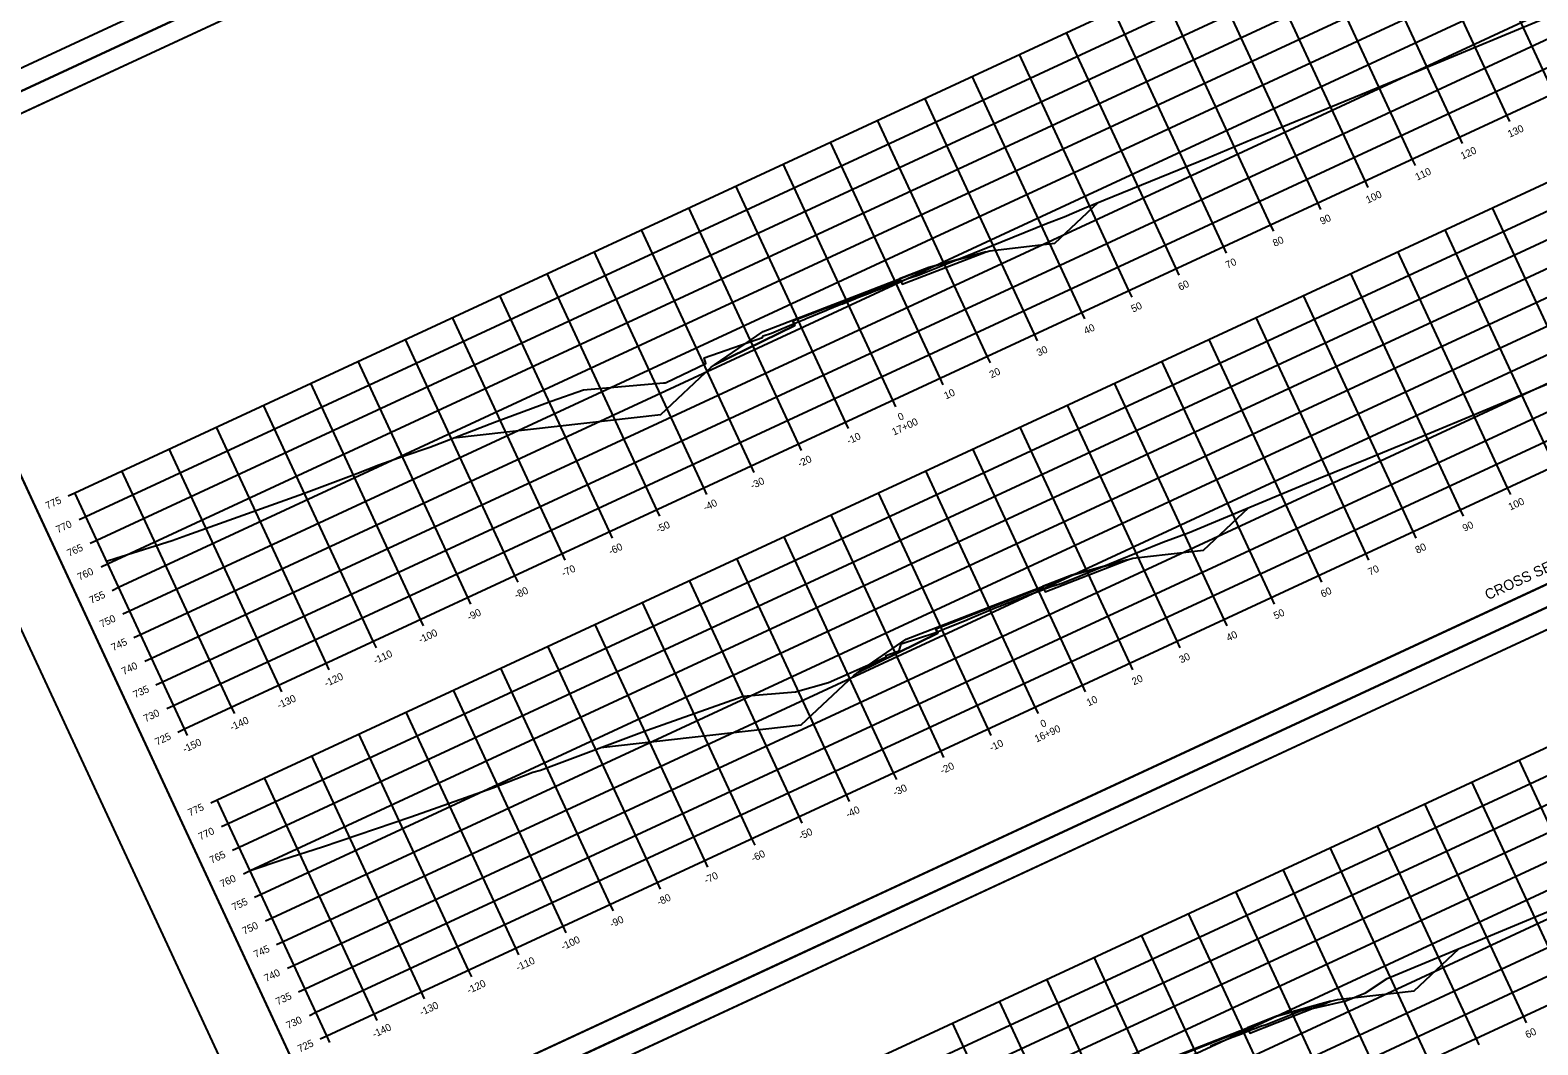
# Model space of a CAD drawing. Extents: x 1354696 to 1366163, y 660729 to 670380.
# Drawn here: x 1358133.8 to 1358423.4, y 665571.2 to 665766.1 of the extents above; entities that cross this region are included whole.
import ezdxf

# ---------------------------------------------------------------- set-up
doc = ezdxf.new("R2010")
doc.units = 0
for name, color, linetype in [('Default', 7, 'Continuous'), ('R_Alt Surface', 7, 'Continuous'), ('R_Axis', 7, 'Continuous'), ('R_Axis Annot', 7, 'Continuous'), ('R_Border', 7, 'Continuous'), ('R_Draft', 7, 'Continuous'), ('R_Exist Surface', 7, 'Continuous'), ('R_Fin Surface', 7, 'Continuous'), ('R_Grid', 7, 'Continuous'), ('R_No Plot', 7, 'Continuous')]:
    doc.layers.add(name, color=color, linetype=linetype)

msp = doc.modelspace()

# ---------------------------------------------------------------- linework, layer by layer
at = {"layer": 'Default'}
for points in [[(1358301.32, 665717.32), (1358317.44, 665723.54), (1358306.44, 665720.5), (1358300.83, 665718.34), (1358300.91, 665718.18)], [(1358280.33, 665710.25), (1358280.72, 665709.38), (1358265.28, 665701.83), (1358274.65, 665708.24), (1358280.26, 665710.4)], [(1358328.75, 665658.24), (1358344.58, 665664.39), (1358333.87, 665661.43), (1358328.26, 665659.26), (1358328.34, 665659.1)], [(1358307.79, 665651.12), (1358308.18, 665650.25), (1358292.83, 665642.75), (1358302.11, 665649.09), (1358307.72, 665651.27)], [(1358368.1, 665573.47), (1358383.66, 665579.56), (1358373.22, 665576.68), (1358367.62, 665574.48), (1358367.69, 665574.33)]]:
    msp.add_lwpolyline(points, close=True, dxfattribs=at)
at = {"layer": 'R_Alt Surface'}
for points in [[(1358265.28, 665701.83), (1358280.72, 665709.38), (1358280.33, 665710.25), (1358290.62, 665714.22), (1358300.91, 665718.18), (1358301.32, 665717.32), (1358317.44, 665723.54)], [(1358292.83, 665642.75), (1358308.18, 665650.25), (1358307.79, 665651.12), (1358318.06, 665655.11), (1358328.34, 665659.1), (1358328.75, 665658.24), (1358344.58, 665664.39)], [(1358332.31, 665557.97), (1358347.56, 665565.42), (1358347.17, 665566.29), (1358357.43, 665570.31), (1358367.69, 665574.33), (1358368.1, 665573.47), (1358383.66, 665579.56)]]:
    msp.add_lwpolyline(points, dxfattribs=at)
at = {"layer": 'R_Axis'}
for p, q in [((1358163.47, 665631.88), (1358435.57, 665758.21)), ((1358418.02, 665748.52), (1358417.43, 665749.79)), ((1358408.95, 665744.31), (1358408.36, 665745.58)), ((1358399.88, 665740.09), (1358399.29, 665741.36)), ((1358390.81, 665735.88), (1358390.22, 665737.15)), ((1358381.74, 665731.67), (1358381.15, 665732.94)), ((1358372.67, 665727.46), (1358372.08, 665728.73)), ((1358363.6, 665723.25), (1358363.01, 665724.52)), ((1358354.53, 665719.04), (1358353.94, 665720.31)), ((1358345.46, 665714.83), (1358344.87, 665716.1)), ((1358336.39, 665710.62), (1358335.8, 665711.89)), ((1358327.32, 665706.41), (1358326.73, 665707.68)), ((1358318.25, 665702.2), (1358317.66, 665703.47)), ((1358190.84, 665572.92), (1358462.94, 665699.25)), ((1358309.18, 665697.98), (1358308.59, 665699.25)), ((1358300.11, 665693.77), (1358299.52, 665695.04)), ((1358291.04, 665689.56), (1358290.45, 665690.83)), ((1358281.97, 665685.35), (1358281.38, 665686.62)), ((1358272.9, 665681.14), (1358272.31, 665682.41)), ((1358141.14, 665676.64), (1358142.41, 665677.23)), ((1358163.47, 665631.88), (1358142.41, 665677.23)), ((1358263.83, 665676.93), (1358263.24, 665678.2)), ((1358418.18, 665676.93), (1358417.59, 665678.2)), ((1358254.76, 665672.72), (1358254.17, 665673.99)), ((1358409.11, 665672.72), (1358408.52, 665673.99)), ((1358143.25, 665672.1), (1358144.52, 665672.69)), ((1358145.36, 665667.57), (1358146.63, 665668.16)), ((1358245.69, 665668.51), (1358245.1, 665669.78)), ((1358400.04, 665668.51), (1358399.45, 665669.78)), ((1358236.62, 665664.3), (1358236.03, 665665.57)), ((1358390.97, 665664.29), (1358390.38, 665665.56)), ((1358147.46, 665663.03), (1358148.73, 665663.62)), ((1358227.55, 665660.09), (1358226.96, 665661.36)), ((1358381.9, 665660.08), (1358381.31, 665661.35)), ((1358149.57, 665658.5), (1358150.84, 665659.09)), ((1358218.48, 665655.87), (1358217.89, 665657.14)), ((1358372.83, 665655.87), (1358372.24, 665657.14)), ((1358151.67, 665653.96), (1358152.94, 665654.55)), ((1358209.41, 665651.66), (1358208.82, 665652.93)), ((1358363.76, 665651.66), (1358363.17, 665652.93)), ((1358153.78, 665649.43), (1358155.05, 665650.02)), ((1358200.34, 665647.45), (1358199.75, 665648.72)), ((1358354.69, 665647.45), (1358354.1, 665648.72)), ((1358155.88, 665644.89), (1358157.15, 665645.48)), ((1358191.27, 665643.24), (1358190.68, 665644.51)), ((1358345.62, 665643.24), (1358345.03, 665644.51)), ((1358157.99, 665640.36), (1358159.26, 665640.95)), ((1358182.2, 665639.03), (1358181.61, 665640.3)), ((1358336.55, 665639.03), (1358335.96, 665640.3)), ((1358160.09, 665635.82), (1358161.36, 665636.41)), ((1358173.13, 665634.82), (1358172.54, 665636.09)), ((1358327.48, 665634.82), (1358326.89, 665636.09)), ((1358162.2, 665631.29), (1358163.47, 665631.88)), ((1358164.06, 665630.61), (1358163.47, 665631.88)), ((1358318.41, 665630.61), (1358317.82, 665631.88)), ((1358309.34, 665626.4), (1358308.75, 665627.67)), ((1358300.27, 665622.18), (1358299.68, 665623.45)), ((1358168.52, 665617.68), (1358169.79, 665618.27)), ((1358190.84, 665572.92), (1358169.79, 665618.27)), ((1358291.2, 665617.97), (1358290.61, 665619.24)), ((1358282.13, 665613.76), (1358281.54, 665615.03)), ((1358170.62, 665613.15), (1358171.89, 665613.74)), ((1358230.15, 665488.26), (1358502.25, 665614.59)), ((1358172.73, 665608.61), (1358174, 665609.2)), ((1358273.06, 665609.55), (1358272.47, 665610.82)), ((1358263.99, 665605.34), (1358263.4, 665606.61)), ((1358174.83, 665604.08), (1358176.1, 665604.67)), ((1358254.92, 665601.13), (1358254.33, 665602.4)), ((1358176.94, 665599.54), (1358178.21, 665600.13)), ((1358245.85, 665596.92), (1358245.26, 665598.19)), ((1358179.04, 665595.01), (1358180.31, 665595.6)), ((1358236.78, 665592.71), (1358236.19, 665593.98)), ((1358181.15, 665590.47), (1358182.42, 665591.06)), ((1358227.71, 665588.5), (1358227.12, 665589.77)), ((1358183.25, 665585.94), (1358184.52, 665586.53)), ((1358218.64, 665584.29), (1358218.05, 665585.56)), ((1358185.36, 665581.4), (1358186.63, 665581.99)), ((1358209.57, 665580.07), (1358208.98, 665581.34)), ((1358187.47, 665576.87), (1358188.74, 665577.46)), ((1358200.5, 665575.86), (1358199.91, 665577.13)), ((1358421.21, 665575.42), (1358420.62, 665576.69)), ((1358189.57, 665572.33), (1358190.84, 665572.92)), ((1358191.43, 665571.65), (1358190.84, 665572.92)), ((1358412.14, 665571.21), (1358411.55, 665572.48))]:
    msp.add_line(p, q, dxfattribs=at)
at = {"layer": 'R_Border'}
for p, q in [((1358388.95, 665878.06), (1358102.17, 665744.91)), ((1358105.49, 665737.77), (1358392.27, 665870.91)), ((1358192.01, 665551.41), (1358105.49, 665737.77)), ((1358478.79, 665684.56), (1358192.01, 665551.41)), ((1358195.32, 665544.27), (1358482.1, 665677.41)), ((1358333.77, 665608.26), (1358333.77, 665608.26)), ((1358333.77, 665608.26), (1358333.77, 665608.26))]:
    msp.add_line(p, q, dxfattribs=at)
at = {"layer": 'R_Exist Surface'}
for points in [[(1358148.5, 665664.11), (1358150.27, 665664.67), (1358161.1, 665668.1), (1358163.96, 665669.09), (1358186.34, 665677.1), (1358196.56, 665680.93), (1358200.84, 665682.61), (1358205.66, 665684.31), (1358210.59, 665686.03), (1358223, 665690.77), (1358233.91, 665694.83), (1358240.09, 665697.02), (1358255.47, 665698.36), (1358255.8, 665698.35), (1358255.99, 665698.44), (1358263.64, 665702.1), (1358263.27, 665703.18), (1358274.5, 665707.04), (1358274.6, 665707.38), (1358276.2, 665707.9), (1358281.01, 665709.95), (1358282.32, 665710.48), (1358282.47, 665710.55), (1358282.89, 665710.71), (1358286.77, 665712.33), (1358287.03, 665712.44), (1358289.56, 665713.44), (1358289.83, 665713.55), (1358292.34, 665714.57), (1358292.62, 665714.68), (1358295.14, 665715.66), (1358295.43, 665715.77), (1358297.97, 665716.71), (1358298.25, 665716.81), (1358302.38, 665718.37), (1358302.55, 665718.44), (1358302.78, 665718.51), (1358304.58, 665719.09), (1358315.14, 665723.3), (1358318.49, 665724.67), (1358329.04, 665728.95), (1358332.43, 665730.25), (1358336.28, 665731.9), (1358360, 665741.59), (1358368.56, 665745.14), (1358382.9, 665751.04), (1358397.76, 665757.21), (1358429.86, 665770.52)], [(1358176.08, 665604.71), (1358182.37, 665606.8), (1358189.99, 665609.21), (1358206.98, 665615), (1358222.73, 665620.59), (1358225.32, 665621.62), (1358230.39, 665623.57), (1358231.86, 665623.96), (1358252.37, 665631.63), (1358270.75, 665638.15), (1358280.82, 665639.03), (1358287.15, 665640.78), (1358296.48, 665644.9), (1358298.26, 665645.75), (1358298.18, 665646), (1358300.76, 665646.89), (1358301.15, 665648.23), (1358307.59, 665650.34), (1358308.36, 665650.67), (1358308.58, 665650.75), (1358309.87, 665651.29), (1358313.3, 665652.66), (1358314.31, 665653.08), (1358316.41, 665654), (1358317.07, 665654.26), (1358319.19, 665655.12), (1358319.85, 665655.39), (1358321.98, 665656.25), (1358322.64, 665656.51), (1358324.79, 665657.33), (1358325.45, 665657.58), (1358327.61, 665658.37), (1358328.69, 665658.78), (1358329.96, 665659.26), (1358331.62, 665659.78), (1358331.98, 665659.89), (1358334.07, 665660.73), (1358342.52, 665664.18), (1358351.39, 665667.77), (1358356.41, 665669.62), (1358381.28, 665679.97), (1358390.65, 665683.77), (1358395.75, 665685.85), (1358396.84, 665686.31), (1358398.74, 665687.09), (1358402.93, 665688.83), (1358410.9, 665692.16), (1358425.9, 665698.43)], [(1358360.5, 665571.03), (1358362.08, 665571.67), (1358363.29, 665572.13), (1358364.89, 665572.74), (1358366.5, 665573.33), (1358368.3, 665574.06), (1358369.23, 665574.41), (1358370.13, 665574.78), (1358371.21, 665575.13), (1358377.6, 665577.65), (1358377.93, 665577.78), (1358378.91, 665578.07), (1358380.36, 665578.22), (1358386.51, 665579.67), (1358390.32, 665581.18), (1358394.46, 665583.93), (1358429.98, 665598.76)]]:
    msp.add_lwpolyline(points, dxfattribs=at)
at = {"layer": 'R_Fin Surface'}
for points in [[(1358215.18, 665687.78), (1358254.99, 665692.3), (1358264.61, 665701.37), (1358265.28, 665701.83), (1358274.65, 665708.24), (1358280.26, 665710.4), (1358290.55, 665714.37), (1358300.83, 665718.34), (1358306.44, 665720.5), (1358317.44, 665723.54), (1358318.17, 665723.74), (1358330.66, 665725.16), (1358338.98, 665733.01)], [(1358243.45, 665628.29), (1358281.93, 665632.66), (1358292.07, 665642.23), (1358292.83, 665642.75), (1358302.11, 665649.09), (1358307.72, 665651.27), (1358317.99, 665655.26), (1358328.26, 665659.26), (1358333.87, 665661.43), (1358344.58, 665664.39), (1358345.59, 665664.67), (1358359.17, 665666.21), (1358367.8, 665674.36)], [(1358284.04, 665543.14), (1358320.77, 665547.3), (1358331.46, 665557.39), (1358332.31, 665557.97), (1358341.5, 665564.25), (1358347.1, 665566.45), (1358357.36, 665570.46), (1358367.62, 665574.48), (1358373.22, 665576.68), (1358383.66, 665579.56), (1358384.94, 665579.92), (1358399.64, 665581.58), (1358408.22, 665589.67)]]:
    msp.add_lwpolyline(points, dxfattribs=at)
at = {"layer": 'R_Grid'}
for p, q in [((1358142.41, 665677.23), (1358414.52, 665803.56)), ((1358144.52, 665672.69), (1358416.62, 665799.02)), ((1358426.5, 665754), (1358405.45, 665799.35)), ((1358146.63, 665668.16), (1358418.73, 665794.49)), ((1358417.43, 665749.79), (1358396.38, 665795.14)), ((1358148.73, 665663.62), (1358420.83, 665789.95)), ((1358408.36, 665745.58), (1358387.31, 665790.93)), ((1358399.29, 665741.36), (1358378.24, 665786.72)), ((1358150.84, 665659.09), (1358422.94, 665785.42)), ((1358152.94, 665654.55), (1358425.05, 665780.88)), ((1358390.22, 665737.15), (1358369.17, 665782.5)), ((1358381.15, 665732.94), (1358360.1, 665778.29)), ((1358155.05, 665650.02), (1358427.15, 665776.35)), ((1358157.15, 665645.48), (1358429.26, 665771.81)), ((1358372.08, 665728.73), (1358351.03, 665774.08)), ((1358363.01, 665724.52), (1358341.96, 665769.87)), ((1358159.26, 665640.95), (1358431.36, 665767.28)), ((1358353.94, 665720.31), (1358332.89, 665765.66)), ((1358161.36, 665636.41), (1358433.47, 665762.74)), ((1358344.87, 665716.1), (1358323.82, 665761.45)), ((1358163.47, 665631.88), (1358435.57, 665758.21)), ((1358335.8, 665711.89), (1358314.75, 665757.24)), ((1358326.73, 665707.68), (1358305.68, 665753.03)), ((1358317.66, 665703.47), (1358296.61, 665748.82)), ((1358169.79, 665618.27), (1358441.89, 665744.6)), ((1358308.59, 665699.25), (1358287.54, 665744.6)), ((1358171.89, 665613.74), (1358444, 665740.07)), ((1358299.52, 665695.04), (1358278.47, 665740.39)), ((1358174, 665609.2), (1358446.1, 665735.53)), ((1358290.45, 665690.83), (1358269.4, 665736.18)), ((1358176.1, 665604.67), (1358448.21, 665731)), ((1358281.38, 665686.62), (1358260.33, 665731.97)), ((1358435.73, 665686.62), (1358414.68, 665731.97)), ((1358178.21, 665600.13), (1358450.31, 665726.46)), ((1358272.31, 665682.41), (1358251.26, 665727.76)), ((1358426.66, 665682.41), (1358405.61, 665727.76)), ((1358263.24, 665678.2), (1358242.19, 665723.55)), ((1358417.59, 665678.2), (1358396.54, 665723.55)), ((1358180.31, 665595.6), (1358452.42, 665721.93)), ((1358254.17, 665673.99), (1358233.12, 665719.34)), ((1358408.52, 665673.99), (1358387.47, 665719.34)), ((1358182.42, 665591.06), (1358454.52, 665717.39)), ((1358245.1, 665669.78), (1358224.05, 665715.13)), ((1358399.45, 665669.78), (1358378.4, 665715.13)), ((1358184.52, 665586.53), (1358456.63, 665712.86)), ((1358236.03, 665665.57), (1358214.98, 665710.92)), ((1358390.38, 665665.56), (1358369.33, 665710.92)), ((1358186.63, 665581.99), (1358458.73, 665708.32)), ((1358226.96, 665661.36), (1358205.9, 665706.71)), ((1358381.31, 665661.35), (1358360.26, 665706.7)), ((1358188.74, 665577.46), (1358460.84, 665703.79)), ((1358217.89, 665657.14), (1358196.83, 665702.49)), ((1358372.24, 665657.14), (1358351.19, 665702.49)), ((1358190.84, 665572.92), (1358462.94, 665699.25)), ((1358208.82, 665652.93), (1358187.76, 665698.28)), ((1358363.17, 665652.93), (1358342.12, 665698.28)), ((1358199.75, 665648.72), (1358178.69, 665694.07)), ((1358354.1, 665648.72), (1358333.05, 665694.07)), ((1358190.68, 665644.51), (1358169.62, 665689.86)), ((1358345.03, 665644.51), (1358323.98, 665689.86)), ((1358181.61, 665640.3), (1358160.55, 665685.65)), ((1358335.96, 665640.3), (1358314.91, 665685.65)), ((1358172.54, 665636.09), (1358151.48, 665681.44)), ((1358326.89, 665636.09), (1358305.84, 665681.44)), ((1358163.47, 665631.88), (1358142.41, 665677.23)), ((1358317.82, 665631.88), (1358296.77, 665677.23)), ((1358308.75, 665627.67), (1358287.7, 665673.02)), ((1358299.68, 665623.45), (1358278.63, 665668.8)), ((1358290.61, 665619.24), (1358269.56, 665664.59)), ((1358281.54, 665615.03), (1358260.49, 665660.38)), ((1358272.47, 665610.82), (1358251.42, 665656.17)), ((1358211.2, 665529.08), (1358483.3, 665655.41)), ((1358213.3, 665524.54), (1358485.41, 665650.87)), ((1358263.4, 665606.61), (1358242.35, 665651.96)), ((1358254.33, 665602.4), (1358233.28, 665647.75)), ((1358215.41, 665520.01), (1358487.51, 665646.34)), ((1358217.51, 665515.47), (1358489.62, 665641.8)), ((1358245.26, 665598.19), (1358224.21, 665643.54)), ((1358236.19, 665593.98), (1358215.14, 665639.33)), ((1358219.62, 665510.94), (1358491.72, 665637.27)), ((1358227.12, 665589.77), (1358206.07, 665635.12)), ((1358221.72, 665506.4), (1358493.83, 665632.73)), ((1358218.05, 665585.56), (1358197, 665630.91)), ((1358208.98, 665581.34), (1358187.93, 665626.69)), ((1358223.83, 665501.87), (1358495.93, 665628.2)), ((1358225.93, 665497.33), (1358498.04, 665623.66)), ((1358438.76, 665585.12), (1358419.81, 665625.93)), ((1358199.91, 665577.13), (1358178.86, 665622.48)), ((1358429.69, 665580.91), (1358410.74, 665621.72)), ((1358190.84, 665572.92), (1358169.79, 665618.27)), ((1358228.04, 665492.8), (1358500.14, 665619.13)), ((1358420.62, 665576.69), (1358401.67, 665617.51)), ((1358230.15, 665488.26), (1358502.25, 665614.59)), ((1358411.55, 665572.48), (1358392.6, 665613.3)), ((1358402.48, 665568.27), (1358383.53, 665609.09)), ((1358393.41, 665564.06), (1358374.46, 665604.88)), ((1358384.34, 665559.85), (1358365.39, 665600.67)), ((1358375.27, 665555.64), (1358356.32, 665596.46)), ((1358366.2, 665551.43), (1358347.25, 665592.24)), ((1358357.13, 665547.22), (1358338.18, 665588.03)), ((1358348.06, 665543.01), (1358329.11, 665583.82)), ((1358338.99, 665538.8), (1358320.04, 665579.61)), ((1358329.92, 665534.58), (1358310.97, 665575.4))]:
    msp.add_line(p, q, dxfattribs=at)
at = {"layer": 'R_No Plot'}
for p, q in [((1358092.6, 665736.08), (1358394.94, 665876.45)), ((1358092.6, 665736.08), (1358394.94, 665876.45)), ((1358182.43, 665542.58), (1358484.77, 665682.95)), ((1358182.44, 665542.58), (1358484.77, 665682.95))]:
    msp.add_line(p, q, dxfattribs=at)
for points in [[(1358002.76, 665929.58), (1358305.1, 666069.95), (1358394.94, 665876.45), (1358092.59, 665736.08)], [(1358227.82, 666029.77), (1358245.61, 666038.03), (1358249.77, 666029.07), (1358264.39, 666035.86), (1358285.43, 666045.63), (1358297.4, 666020.14), (1358318.45, 666029.91), (1358388.95, 665878.06), (1358102.17, 665744.91), (1358015.65, 665931.27)], [(1358092.59, 665736.08), (1358394.94, 665876.45), (1358484.77, 665682.95), (1358182.43, 665542.58)], [(1358317.66, 665836.27), (1358335.45, 665844.53), (1358339.61, 665835.57), (1358354.23, 665842.36), (1358375.27, 665852.13), (1358387.23, 665826.64), (1358408.28, 665836.41), (1358478.79, 665684.56), (1358192.01, 665551.41), (1358105.49, 665737.77)], [(1358182.43, 665542.58), (1358484.77, 665682.95), (1358574.61, 665489.45), (1358272.27, 665349.08)], [(1358407.49, 665642.77), (1358425.29, 665651.03), (1358429.45, 665642.07), (1358444.06, 665648.86), (1358465.1, 665658.63), (1358477.07, 665633.14), (1358498.12, 665642.91), (1358568.62, 665491.06), (1358281.84, 665357.91), (1358195.32, 665544.27)]]:
    msp.add_lwpolyline(points, close=True, dxfattribs=at)

# ---------------------------------------------------------------- texts
at = {"layer": 'R_Axis Annot'}
for s, p in [('130', (1358418.01, 665745.42)), ('120', (1358408.94, 665741.21)), ('110', (1358400.23, 665737.17)), ('100', (1358390.75, 665732.77)), ('90', (1358381.94, 665728.68)), ('80', (1358372.87, 665724.46)), ('70', (1358363.8, 665720.25)), ('60', (1358354.7, 665716.03)), ('50', (1358345.66, 665711.83)), ('40', (1358336.59, 665707.62)), ('30', (1358327.52, 665703.41)), ('20', (1358318.45, 665699.2)), ('10', (1358309.73, 665695.15)), ('17+00', (1358299.74, 665688.2)), ('0', (1358300.87, 665691.04)), ('-10', (1358291.07, 665686.49)), ('-20', (1358281.64, 665682.11)), ('-30', (1358272.57, 665677.9)), ('775', (1358137.17, 665674.02)), ('-40', (1358263.5, 665673.69)), ('100', (1358418.12, 665673.81)), ('770', (1358139.17, 665669.44)), ('-50', (1358254.43, 665669.48)), ('90', (1358409.31, 665669.72)), ('765', (1358141.32, 665664.92)), ('-60', (1358245.33, 665665.26)), ('80', (1358400.24, 665665.51)), ('760', (1358143.32, 665660.34)), ('-70', (1358236.29, 665661.06)), ('70', (1358391.17, 665661.3)), ('755', (1358145.59, 665655.88)), ('-80', (1358227.22, 665656.85)), ('60', (1358382.07, 665657.07)), ('750', (1358147.59, 665651.3)), ('-90', (1358218.15, 665652.64)), ('50', (1358373.03, 665652.88)), ('-100', (1358208.82, 665648.3)), ('40', (1358363.96, 665648.66)), ('745', (1358149.8, 665646.81)), ('-110', (1358200.16, 665644.28)), ('740', (1358151.8, 665642.23)), ('30', (1358354.89, 665644.45)), ('-120', (1358190.73, 665639.91)), ('20', (1358345.82, 665640.24)), ('735', (1358154.01, 665637.74)), ('-130', (1358181.66, 665635.69)), ('10', (1358337.11, 665636.2)), ('730', (1358156.01, 665633.16)), ('-140', (1358172.59, 665631.48)), ('16+90', (1358327.13, 665629.25)), ('0', (1358328.25, 665632.09)), ('725', (1358158.22, 665628.67)), ('-150', (1358163.52, 665627.27)), ('-10', (1358318.45, 665627.54)), ('-20', (1358309.02, 665623.16)), ('-30', (1358299.95, 665618.95)), ('775', (1358164.54, 665615.07)), ('-40', (1358290.88, 665614.74)), ('770', (1358166.54, 665610.48)), ('-50', (1358281.81, 665610.52)), ('765', (1358168.69, 665605.97)), ('-60', (1358272.71, 665606.3)), ('760', (1358170.69, 665601.38)), ('-70', (1358263.67, 665602.1)), ('755', (1358172.96, 665596.93)), ('-80', (1358254.6, 665597.89)), ('750', (1358174.96, 665592.34)), ('-90', (1358245.53, 665593.68)), ('-100', (1358236.2, 665589.35)), ('745', (1358177.17, 665587.86)), ('-110', (1358227.54, 665585.33)), ('740', (1358179.17, 665583.27)), ('-120', (1358218.1, 665580.95)), ('735', (1358181.39, 665578.79)), ('-130', (1358209.03, 665576.74)), ('730', (1358183.38, 665574.2)), ('-140', (1358199.96, 665572.53)), ('60', (1358421.37, 665572.41)), ('725', (1358185.6, 665569.72))]:
    msp.add_text(s, height=1.4, rotation=24.9042, dxfattribs=at).set_placement(p)
at = {"layer": 'R_Draft'}
msp.add_text('CROSS SECTION STA. 16+90 TO STA. 17+00', height=2, rotation=24.9042, dxfattribs=at).set_placement((1358413.79, 665656.59))

doc.saveas('drawing.dxf')
